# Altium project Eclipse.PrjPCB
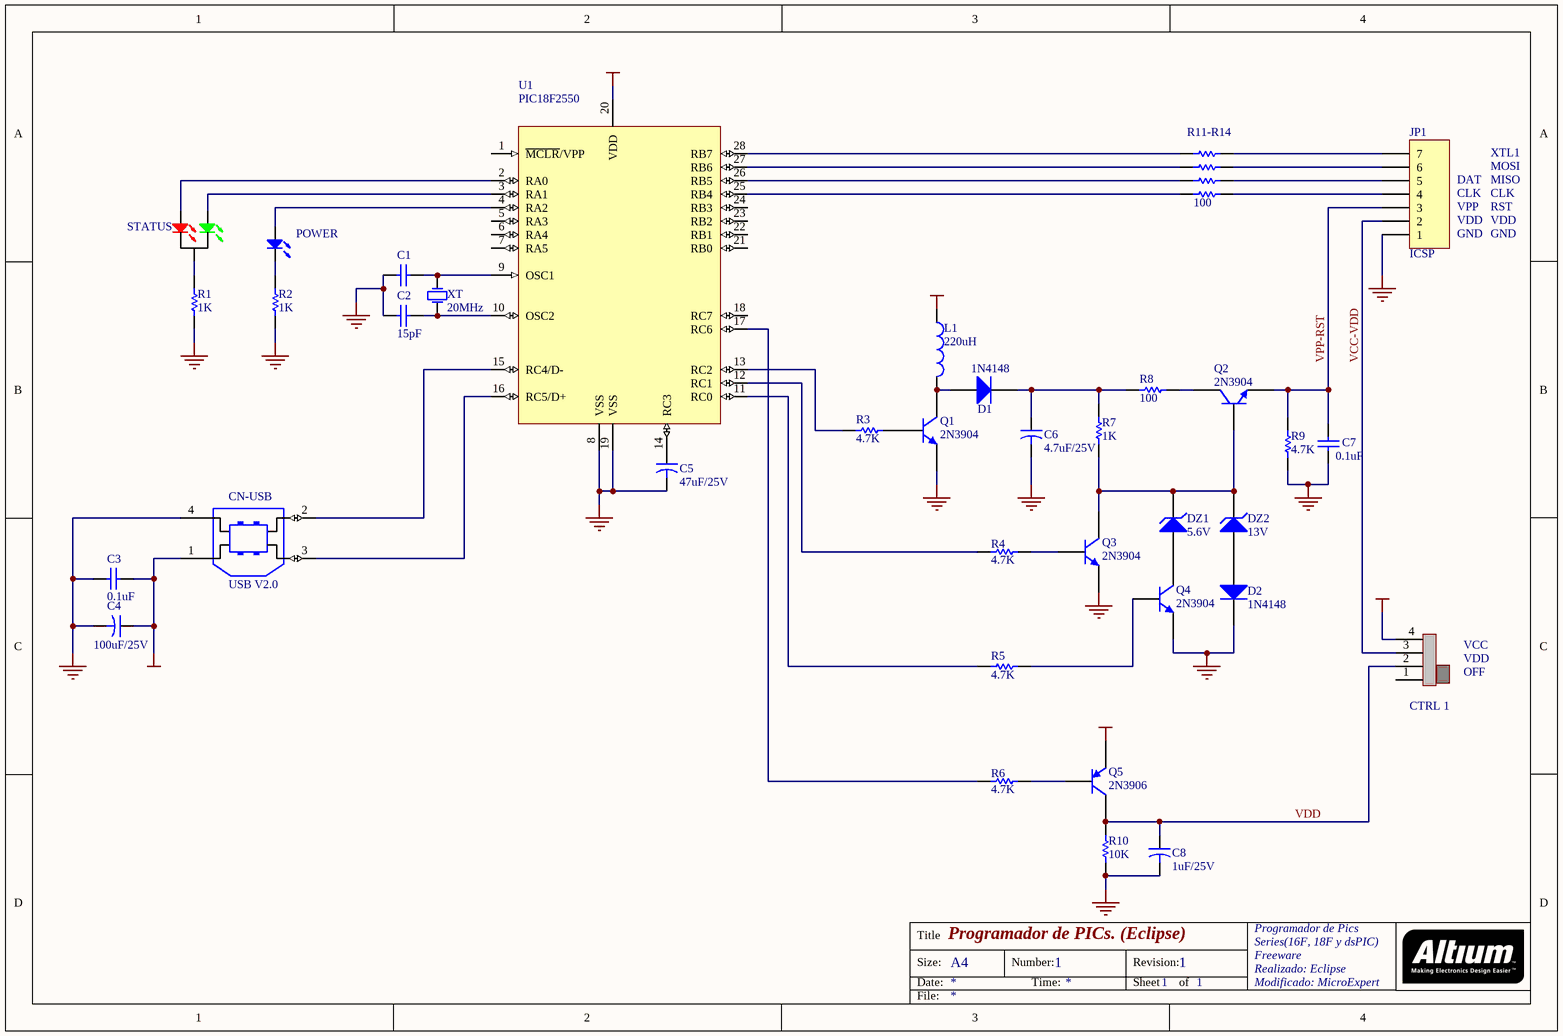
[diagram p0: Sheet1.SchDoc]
1 sheet, 39 parts. Net scope: global (net labels, ports and power ports of the same name join across sheets).
Board file: PCB1.PcbDoc

## Sheet Sheet1.SchDoc: Programador de PICs. (Eclipse)
size A4; Organization: Programador de Pics; Address1: Series(16F, 18F y dsPIC); Address2: Freeware; Address3: Realizado: Eclipse; Address4: Modificado: MicroExpert; DocumentNumber: 1; Revision: 1; SheetNumber: 1; SheetTotal: 1

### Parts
C1  CC  [CC 0.15]  (value not drawn)
C2  value 15pF  [CC 0.15]  (hidden comment: CC)
C3  value 0.1uF  [CC 0.15]  (hidden comment: CC)
C4  value 100uF/25V  [CE-2MIL]  (hidden comment: Cap)
C5  value 47uF/25V  [CE-1.7]  (hidden comment: Cap)
C6  value 4.7uF/25V  [CE-1.7]  (hidden comment: Cap)
C7  value 0.1uF  [CC 0.15]  (hidden comment: CC)
C8  value 1uF/25V  [CE-1.7]  (hidden comment: Cap)
CN-USB  USB V2.0  [USB2.5-2H4D]
CTRL_1  INPUT  [HDR1X4]  (value not drawn)
D1  Class II: 1N4148  [DIODO 4MIL]  (hidden comment: Diodo)
D2  Class II: 1N4148  [DIODO 4MIL]  (hidden comment: Diodo)
DZ1  5.6V  [DIODOZ]
DZ2  13V  [DIODOZ]
JP1  ICSP  [HDR1X7H]
L1  value 220uH  [L]  (hidden comment: Inductor)
POWER  LED  [LED-0]  (value not drawn)
Q1  2N3904  [Q123 0.1]
Q2  2N3904  [Q123 0.1]
Q3  2N3904  [Q123 0.1]
Q4  2N3904  [Q123 0.1]
Q5  2N3906  [Q123 0.1]
R1  value 1K  [AXIAL 4MIL]  (hidden comment: Res)
R2  value 1K  [AXIAL 4MIL]  (hidden comment: Res)
R3  value 4.7K  [AXIAL 4MIL]  (hidden comment: Res)
R4  value 4.7K  [AXIAL 4MIL]  (hidden comment: Res)
R5  value 4.7K  [AXIAL 4MIL]  (hidden comment: Res)
R6  value 4.7K  [AXIAL 4MIL]  (hidden comment: Res)
R7  value 1K  [AXIAL 4MIL]  (hidden comment: Res)
R8  value 100  [AXIAL 4MIL]  (hidden comment: Res)
R9  value 4.7K  [AXIAL 4MIL]  (hidden comment: Res)
R10  value 10K  [AXIAL 4MIL]  (hidden comment: Res)
R11  Res  [AXIAL 4MIL]  (value not drawn)
R12  Res  [AXIAL 4MIL]  (value not drawn)
R13  Res  [AXIAL 4MIL]  (value not drawn)
R14  value 100  [AXIAL 4MIL]  (hidden comment: Res)
STATUS  LED  [LED-BI]  (value not drawn)
U1  PIC18F2550  [DIP-28]
XT  20MHz  [XT 0.17]

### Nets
GND: C1.1 C2.1 C3.1 C4.2 C5.2 C6.2 C7.1 C8.2 CN-USB.4 D2.2(K) JP1.1 Q1.1(E) Q3.1(E) Q4.1(E) R1.1 R2.1 R9.1 R10.1 U1.8(VSS) U1.19(VSS)
VCC: C3.2 C4.1 CN-USB.1 L1.1 Q5.1(E) U1.20(VDD)
VCC-VDD: CTRL_1.3 JP1.2
VDD: C8.1 CTRL_1.2 Q5.3(C) R10.2
VPP-RST: C7.2 JP1.3 Q2.1(E) R9.2
NetC1_2: C1.2 U1.9(OSC1) XT.2(OSC2)
NetC2_2: C2.2 U1.10(OSC2) XT.1(OSC1)
NetC5_1: C5.1 U1.14(RC3)
NetC6_1: C6.1 D1.2(K) R7.2 R8.1
NetCN-USB_2: CN-USB.2 U1.15(RC4/D-)
NetCN-USB_3: CN-USB.3 U1.16(RC5/D+)
NetD1_1: D1.1(A) L1.2 Q1.3(C)
NetD2_1: D2.1(A) DZ2.1(A)
NetDZ1_1: DZ1.1(A) Q4.3(C)
NetDZ1_2: DZ1.2(K) DZ2.2(K) Q2.2(B) Q3.3(C) R7.1
NetJP1_4: JP1.4 R14.2
NetJP1_5: JP1.5 R13.2
NetJP1_6: JP1.6 R12.2
NetJP1_7: JP1.7 R11.2
NetPOWER_1: POWER.1(A) U1.4(RA2)
NetPOWER_2: POWER.2(K) R2.2
NetQ1_2: Q1.2(B) R3.2
NetQ2_3: Q2.3(C) R8.2
NetQ3_2: Q3.2(B) R4.2
NetQ4_2: Q4.2(B) R5.2
NetQ5_2: Q5.2(B) R6.2
NetR1_2: R1.2 STATUS.3(K)
NetR3_1: R3.1 U1.13(RC2)
NetR4_1: R4.1 U1.12(RC1)
NetR5_1: R5.1 U1.11(RC0)
NetR6_1: R6.1 U1.17(RC6)
NetR11_1: R11.1 U1.28(RB7)
NetR12_1: R12.1 U1.27(RB6)
NetR13_1: R13.1 U1.26(RB5)
NetR14_1: R14.1 U1.25(RB4)
NetSTATUS_1: STATUS.1(A) U1.3(RA1)
NetSTATUS_2: STATUS.2(A) U1.2(RA0)

Not connected (* = marked no-connect by the designer): CTRL_1 1 4; U1 1(~{MCLR}/VPP) 5(RA3) 6(RA4) 7(RA5) 18(RC7) 21(RB0) 22(RB1) 23(RB2) 24(RB3)

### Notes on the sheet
- (near R11) R11-R14
- MOSI
- XTL1
- (near JP1) GND
- (near JP1) VDD
- (near JP1) VPP
- (near JP1) CLK
- (near JP1) DAT
- MISO
- VDD
- CLK
- RST
- GND
- (near CTRL_1) VCC
- (near CTRL_1) VDD
- (near CTRL_1) OFF

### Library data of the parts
C1 = Cap C: Capacitor Ceramico; Manufacturer: Generic Components; Class I: Passive; Value: 15pF
C2 C3 C7 = Cap C: Capacitor Ceramico; Manufacturer: Generic Components; Class I: Passive
C4-C6 C8 = Cap E: Capacitor Electrolitico; Manufacturer: Generic Components; Class I: Passive
CN-USB = CON USB
CTRL_1 = CON VDD/VCC: Manufacturer: Generic Components; Class I: Connector
D1 D2 = Diodo: Diodo de uso general; Manufacturer: Generic Components; Class I: Discrete
DZ1 DZ2 = D Zener: Diodo Zener; Manufacturer: Generic Components; Class I: Discrete; Class II: Diode - Zener
JP1 = Header 7: Header, 7-Pin
POWER = LED: Manufacturer: Generic Components; Class I: Optoelectronic
Q1-Q4 = 2N3904: NPN Uso general; Manufacturer: Generic Components; Revision 1: 11-July-2000: SIM Model Added.; Revision 2: July-2002: Re-released for DXP Platform.; Class I: Discrete; Class II: BJT - Low Power
Q5 = 2N3906: PNP Uso General; Manufacturer: Generic Components; Revision 1: 11-July-2000: SIM Model Added.; Revision 2: July-2002: Re-released for DXP Platform.; Class I: Discrete; Class II: BJT - Low Power
R1-R10 R14 = Res: Resistor; Manufacturer: Generic Components; Class I: Passive
R11-R13 = Res: Resistor; Manufacturer: Generic Components; Class I: Passive; Value: 100
STATUS = LED_BI: Manufacturer: Generic Components; Class I: Optoelectronic
U1 = PIC18F2550: High Performance, Microcontroller with 10-Bit A/D, 16K EPROM, 28-Pin SOIC, Standard Volt Range, Extended Temperature; PackageDocument: DS00049W_2003; Note: Pin compatible with 28-pin PIC16C7X devices.; Note: Not recommended for new designs. Consider PIC18F242 instead.; Note: RB3 is the alternate pin for the CCP2 pin multiplexing.
XT = XTAL: Crystal Oscillator; Manufacturer: Generic Components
